Omron CX-Programmer project 新規ﾌﾟﾛｼﾞｪｸﾄ (CX-Programmer 9.75)

# PLC 新規PLC1: CJ2M CPU11
I/O table (CPU CJ2M-CPU11): rack 0 slot 0 CJ1W-SCU22

## Program 新規ﾌﾟﾛｸﾞﾗﾑ1 (cyclic task 0)
Local symbols
ｼｰｹﾝｽAbout終了_SCU_0_P2 1519.10 BOOL
ｼｰｹﾝｽEnd終了_SCU_0_P2 1519.11 BOOL
ﾈｯﾄﾜｰｸ通信命令実行可ﾌﾗｸﾞ_P7 A202.07 BOOL
ﾌﾟﾛﾄｺﾙﾏｸﾛｴﾗｰｺｰﾄﾞ_SCU_0_P2 1519 UINT
ﾌﾟﾛﾄｺﾙﾏｸﾛ実行中_SCU_0_P2 1519.15 BOOL
桁数 5504 WORD
受信ｴﾗｰ 5501 WORD
受信エリア下位 5501 WORD
受信エリア上位 5750 WORD
出力_ﾌﾟﾛﾄｺﾙﾏｸﾛ_ｴﾗｰｺｰﾄﾞ H400 UINT
出力_異常終了 5000.03 BOOL
出力_正常終了 5000.02 BOOL
伝送ｴﾗｰ_SCU_0_P2 1518.15 BOOL
伝送ｴﾗｰ発生状態_SCU_0_P2 1518 WORD
読み取ったコード値 5505 WORD
内部_PMCR命令_異常終了 5000.05 BOOL
内部_PMCR命令_正常終了 5000.04 BOOL
内部_PMCR命令実行中 5000.01 BOOL
内部_ｺﾝﾄﾛｰﾙﾃﾞｰﾀ_1 5010 UINT
内部_ｺﾝﾄﾛｰﾙﾃﾞｰﾀ_2 5011 UINT
内部_ﾌﾟﾛﾄｺﾙﾏｸﾛ_ｴﾗｰｺｰﾄﾞ 5012 UINT
内部_ﾌﾟﾛﾄｺﾙﾏｸﾛｴﾗｰｺｰﾄﾞあり 5000.07 BOOL
内部_受信ﾃﾞｰﾀ先頭CH番号 5500 UINT
内部_受信変数ｴﾘｱ_応答ｺｰﾄﾞ部 5501 UINT
内部_送信ﾃﾞｰﾀ先頭CH番号 5020 UINT
入力_起動 5000.00 BOOL
予約（受信回数） 5502 WORD
予約（読み取り回数） 5503 WORD

### Section ｾｸｼｮﾝ1

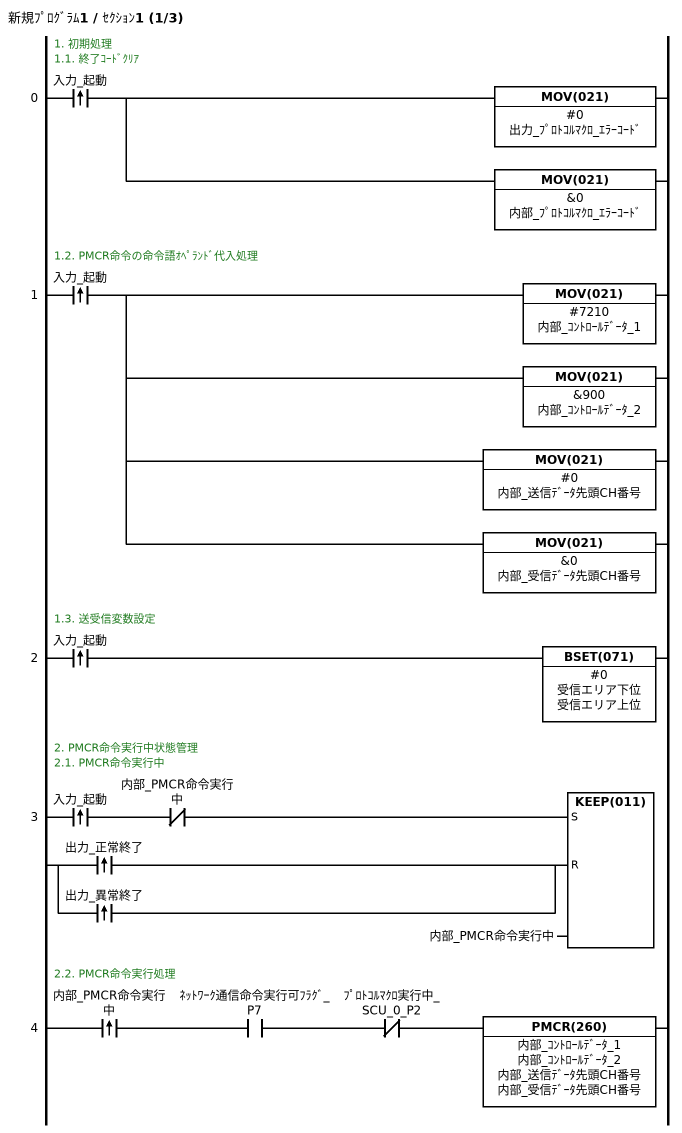
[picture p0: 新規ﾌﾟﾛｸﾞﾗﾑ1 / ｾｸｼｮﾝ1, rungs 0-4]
; rung 0: 1. 初期処理 / 1.1. 終了ｺｰﾄﾞｸﾘｱ
@LD 入力_起動
MOV(021) #0 出力_ﾌﾟﾛﾄｺﾙﾏｸﾛ_ｴﾗｰｺｰﾄﾞ
MOV(021) &0 内部_ﾌﾟﾛﾄｺﾙﾏｸﾛ_ｴﾗｰｺｰﾄﾞ
; rung 1: 1.2. PMCR命令の命令語ｵﾍﾟﾗﾝﾄﾞ代入処理
@LD 入力_起動
MOV(021) #7210 内部_ｺﾝﾄﾛｰﾙﾃﾞｰﾀ_1
MOV(021) &900 内部_ｺﾝﾄﾛｰﾙﾃﾞｰﾀ_2
MOV(021) #0 内部_送信ﾃﾞｰﾀ先頭CH番号
MOV(021) &0 内部_受信ﾃﾞｰﾀ先頭CH番号
; rung 2: 1.3. 送受信変数設定
@LD 入力_起動
BSET(071) #0 受信エリア下位 受信エリア上位
; rung 3: 2. PMCR命令実行中状態管理 / 2.1. PMCR命令実行中
@LD 入力_起動
ANDNOT 内部_PMCR命令実行中
@LD 出力_正常終了
@OR 出力_異常終了
KEEP(011) 内部_PMCR命令実行中
; rung 4: 2.2. PMCR命令実行処理
@LD 内部_PMCR命令実行中
AND ﾈｯﾄﾜｰｸ通信命令実行可ﾌﾗｸﾞ_P7
ANDNOT ﾌﾟﾛﾄｺﾙﾏｸﾛ実行中_SCU_0_P2
PMCR(260) 内部_ｺﾝﾄﾛｰﾙﾃﾞｰﾀ_1 内部_ｺﾝﾄﾛｰﾙﾃﾞｰﾀ_2 内部_送信ﾃﾞｰﾀ先頭CH番号 内部_受信ﾃﾞｰﾀ先頭CH番号

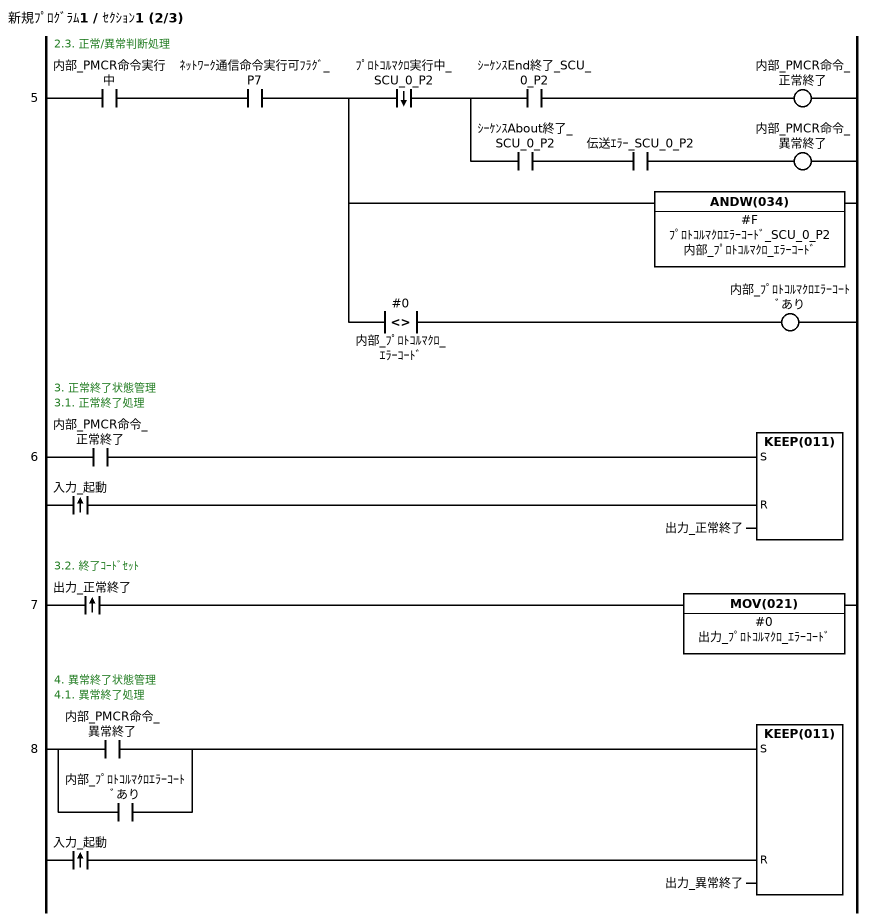
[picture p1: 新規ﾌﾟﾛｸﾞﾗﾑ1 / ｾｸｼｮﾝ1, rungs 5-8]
; rung 5: 2.3. 正常/異常判断処理
LD 内部_PMCR命令実行中
AND ﾈｯﾄﾜｰｸ通信命令実行可ﾌﾗｸﾞ_P7
OUT TR0
%AND ﾌﾟﾛﾄｺﾙﾏｸﾛ実行中_SCU_0_P2
OUT TR1
AND ｼｰｹﾝｽEnd終了_SCU_0_P2
OUT 内部_PMCR命令_正常終了
LD TR1
AND ｼｰｹﾝｽAbout終了_SCU_0_P2
AND 伝送ｴﾗｰ_SCU_0_P2
OUT 内部_PMCR命令_異常終了
LD TR0
ANDW(034) #F ﾌﾟﾛﾄｺﾙﾏｸﾛｴﾗｰｺｰﾄﾞ_SCU_0_P2 内部_ﾌﾟﾛﾄｺﾙﾏｸﾛ_ｴﾗｰｺｰﾄﾞ
AND<>(305) #0 内部_ﾌﾟﾛﾄｺﾙﾏｸﾛ_ｴﾗｰｺｰﾄﾞ
OUT 内部_ﾌﾟﾛﾄｺﾙﾏｸﾛｴﾗｰｺｰﾄﾞあり
; rung 6: 3. 正常終了状態管理 / 3.1. 正常終了処理
LD 内部_PMCR命令_正常終了
@LD 入力_起動
KEEP(011) 出力_正常終了
; rung 7: 3.2. 終了ｺｰﾄﾞｾｯﾄ
@LD 出力_正常終了
MOV(021) #0 出力_ﾌﾟﾛﾄｺﾙﾏｸﾛ_ｴﾗｰｺｰﾄﾞ
; rung 8: 4. 異常終了状態管理 / 4.1. 異常終了処理
LD 内部_PMCR命令_異常終了
OR 内部_ﾌﾟﾛﾄｺﾙﾏｸﾛｴﾗｰｺｰﾄﾞあり
@LD 入力_起動
KEEP(011) 出力_異常終了

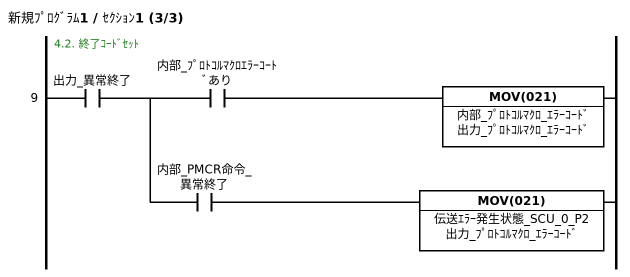
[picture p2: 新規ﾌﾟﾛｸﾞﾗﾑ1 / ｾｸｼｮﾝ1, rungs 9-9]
; rung 9: 4.2. 終了ｺｰﾄﾞｾｯﾄ
LD 出力_異常終了
OUT TR0
AND 内部_ﾌﾟﾛﾄｺﾙﾏｸﾛｴﾗｰｺｰﾄﾞあり
MOV(021) 内部_ﾌﾟﾛﾄｺﾙﾏｸﾛ_ｴﾗｰｺｰﾄﾞ 出力_ﾌﾟﾛﾄｺﾙﾏｸﾛ_ｴﾗｰｺｰﾄﾞ
LD TR0
AND 内部_PMCR命令_異常終了
MOV(021) 伝送ｴﾗｰ発生状態_SCU_0_P2 出力_ﾌﾟﾛﾄｺﾙﾏｸﾛ_ｴﾗｰｺｰﾄﾞ

### Section END
; rung 0
END(001)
